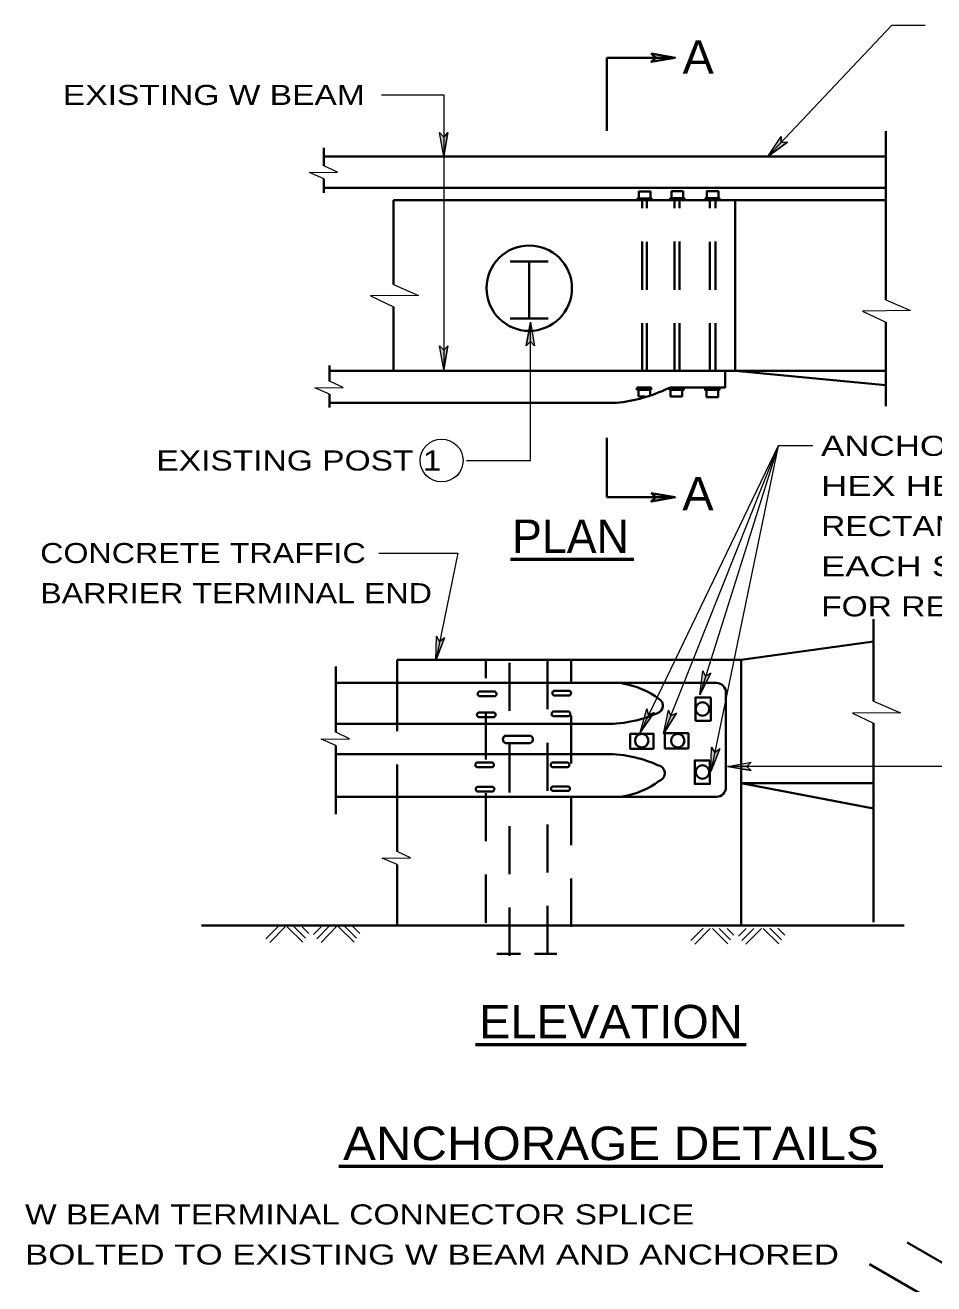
# Model space of a CAD drawing. Extents: x 12.4 to 19.52, y 6.05 to 15.92.
# Drawn here: x 12.402 to 15.119, y 12.12 to 15.885 of the extents above; entities that cross this region are included whole.
import ezdxf
from ezdxf.enums import TextEntityAlignment as Align

# ---------------------------------------------------------------- set-up
doc = ezdxf.new("R2010")
doc.units = 0
doc.header["$LTSCALE"] = 0.024
doc.linetypes.add('LONG_DASHED', pattern=[7.5, 6, -1.5])
for name, color, linetype, lineweight in [('1', 7, 'Continuous', 35), ('10', 7, 'Continuous', 13), ('12', 7, 'Continuous', 53), ('6', 7, 'Continuous', 13)]:
    doc.layers.add(name, color=color, linetype=linetype, lineweight=lineweight)

msp = doc.modelspace()

# ---------------------------------------------------------------- hatches: boundary and pattern name
at = {"layer": '10'}
for points in [[(14.274, 15.7998), (14.3455, 15.7872), (14.274, 15.7746), (14.2875, 15.7872)], [(13.6661, 15.5633), (13.6535, 15.4918), (13.6409, 15.5633), (13.6535, 15.5498)], [(14.6812, 15.5348), (14.623, 15.4914), (14.6629, 15.5521), (14.6628, 15.5336)], [(13.9001, 14.9254), (13.9127, 14.9969), (13.9253, 14.9254), (13.9127, 14.9389)], [(13.6661, 14.9258), (13.6535, 14.8543), (13.6409, 14.9258), (13.6535, 14.9123)], [(14.274, 14.4853), (14.3455, 14.4727), (14.274, 14.4601), (14.2875, 14.4727)], [(13.6562, 14.0519), (13.6294, 13.9844), (13.6316, 14.057), (13.6412, 14.0412)], [(14.4526, 13.9464), (14.4191, 13.882), (14.4286, 13.954), (14.4365, 13.9373)], [(14.2832, 13.8286), (14.2408, 13.7697), (14.2605, 13.8396), (14.266, 13.8219)], [(14.3493, 13.8269), (14.3112, 13.7651), (14.3259, 13.8362), (14.3326, 13.819)], [(14.4788, 13.7203), (14.452, 13.6528), (14.4542, 13.7254), (14.4638, 13.7096)], [(14.5733, 13.6555), (14.5018, 13.6681), (14.5733, 13.6807), (14.5598, 13.6681)]]:
    msp.add_hatch(color=256, dxfattribs=at).paths.add_polyline_path(points)

# ---------------------------------------------------------------- linework, layer by layer
at = {"layer": '1'}
for p, q in [((14.9755, 15.5677), (14.9755, 15.0633)), ((13.2949, 15.4643), (13.2949, 15.5174)), ((14.9775, 15.4918), (13.2949, 15.4918)), ((13.2949, 15.3833), (13.2949, 15.4253)), ((14.9775, 15.3981), (13.2949, 15.3981)), ((14.5254, 15.3617), (13.5037, 15.3617)), ((13.5037, 15.3617), (13.5037, 15.1093)), ((14.5254, 14.8508), (14.5254, 15.3617)), ((14.5254, 15.3617), (14.8546, 15.3617)), ((14.9755, 15.3617), (14.8546, 15.3617)), ((13.9658, 15.178), (13.909, 15.178)), ((13.5037, 14.8536), (13.5037, 15.0427)), ((13.9658, 15.0077), (13.8522, 15.0077)), ((14.9755, 14.7454), (14.9755, 14.9966)), ((13.3116, 14.8203), (13.3116, 14.8664)), ((14.5254, 14.8508), (13.3129, 14.8508)), ((14.5254, 14.8508), (14.9755, 14.8508)), ((14.5254, 14.8508), (14.9755, 14.8084)), ((13.3116, 14.7814), (13.3116, 14.741)), ((13.3129, 14.755), (14.1694, 14.755)), ((14.9386, 14.1082), (14.9386, 13.8634)), ((13.3305, 13.9671), (13.3305, 13.77)), ((14.5425, 13.9869), (13.5142, 13.9869)), ((14.469, 13.9175), (13.3305, 13.9175)), ((13.8059, 13.8916), (13.7607, 13.8916)), ((14.029, 13.8941), (13.9838, 13.8941)), ((13.7607, 13.8778), (13.8059, 13.8778)), ((13.9838, 13.8804), (14.029, 13.8804)), ((14.4974, 13.6052), (14.4974, 13.889)), ((13.8034, 13.8291), (13.7582, 13.8291)), ((13.7582, 13.8154), (13.8034, 13.8154)), ((14.0266, 13.8317), (13.9813, 13.8317)), ((13.9813, 13.818), (14.0266, 13.818)), ((14.1285, 13.7951), (13.3305, 13.7951)), ((14.9386, 13.2019), (14.9386, 13.797)), ((13.9115, 13.7597), (13.8388, 13.7597)), ((13.3305, 13.5248), (13.3305, 13.7307)), ((14.1285, 13.7043), (13.3305, 13.7043)), ((13.8388, 13.7377), (13.9115, 13.7377)), ((13.7984, 13.6793), (13.7532, 13.6793)), ((13.7532, 13.6655), (13.7984, 13.6655)), ((14.0241, 13.6793), (13.9789, 13.6793)), ((13.9789, 13.6655), (14.0241, 13.6655)), ((13.7996, 13.6068), (13.7545, 13.6068)), ((13.7545, 13.5932), (13.7996, 13.5932)), ((14.0253, 13.6082), (13.9801, 13.6082)), ((13.9801, 13.5944), (14.0253, 13.5944)), ((14.5425, 13.6179), (14.9386, 13.6179)), ((14.5425, 13.6179), (14.9386, 13.5418)), ((14.469, 13.5769), (13.3305, 13.5769)), ((13.5142, 13.5769), (13.5142, 13.4134)), ((15.0302, 13.1922), (12.9294, 13.1922)), ((13.8124, 13.1075), (13.8833, 13.1075)), ((13.9918, 13.1075), (13.9251, 13.1075)), ((15.2677, 12.1125), (15.0393, 12.2444)), ((14.9268, 12.1793), (15.1538, 12.0482))]:
    msp.add_line(p, q, dxfattribs=at)
at = {"layer": '1', "linetype": 'LONG_DASHED'}
for p, q in [((14.2466, 14.8495), (14.2466, 15.3604)), ((14.2605, 14.849), (14.2605, 15.3604)), ((14.4497, 14.849), (14.4497, 15.3604)), ((14.2737, 14.8009), (14.2306, 14.8009)), ((14.236, 14.7738), (14.236, 14.794)), ((14.2705, 14.794), (14.2705, 14.7796)), ((14.236, 14.7738), (14.2561, 14.7738)), ((13.7795, 13.2002), (13.7795, 13.9869)), ((13.8502, 13.1016), (13.8502, 13.9869)), ((13.9638, 13.1066), (13.9638, 13.9869)), ((14.035, 13.1886), (14.035, 13.9869)), ((13.5142, 13.9175), (13.5142, 13.5769))]:
    msp.add_line(p, q, dxfattribs=at)
at = {"layer": '1', "linetype": 'LONG_DASHED', "lineweight": 40}
for p, q in [((14.3438, 14.8495), (14.3438, 15.3604)), ((14.3582, 14.8495), (14.3582, 15.3604)), ((14.4667, 14.8495), (14.4667, 15.3604))]:
    msp.add_line(p, q, dxfattribs=at)
at = {"layer": '1', "lineweight": 40}
for p, q in [((13.5142, 13.9869), (13.5142, 13.9175)), ((13.5142, 13.1922), (13.5142, 13.3741))]:
    msp.add_line(p, q, dxfattribs=at)
at = {"layer": '1'}
for points in [[(14.2756, 15.3598), (14.2756, 15.3662), (14.2329, 15.3662), (14.2329, 15.3604)], [(14.2717, 15.3673), (14.2717, 15.3875), (14.2372, 15.3875), (14.2372, 15.3673)], [(14.3733, 15.3605), (14.3733, 15.3668), (14.3307, 15.3668), (14.3307, 15.3609)], [(14.3695, 15.368), (14.3695, 15.3881), (14.335, 15.3881), (14.335, 15.368)], [(14.4748, 15.368), (14.4748, 15.3881), (14.4403, 15.3881), (14.4403, 15.368)], [(13.909, 15.0077), (13.909, 15.178), (13.8522, 15.178)], [(14.4953, 14.8508), (14.4953, 14.8013), (14.3374, 14.8013)], [(14.3715, 14.8009), (14.3715, 14.7944), (14.3288, 14.7944), (14.3288, 14.8003)], [(14.3665, 14.7945), (14.3665, 14.7745), (14.332, 14.7745), (14.332, 14.7945)], [(14.4781, 14.8002), (14.4781, 14.7938), (14.4352, 14.7938), (14.4352, 14.7998)], [(14.4742, 14.7927), (14.4742, 14.7725), (14.4397, 14.7725), (14.4397, 14.7927)], [(14.5425, 13.1922), (14.5425, 13.9869), (14.9386, 14.0415)]]:
    msp.add_lwpolyline(points, dxfattribs=at)
at = {"layer": '1', "lineweight": 40}
msp.add_lwpolyline([(14.4786, 15.3605), (14.4786, 15.3668), (14.4359, 15.3668), (14.4359, 15.3609)], dxfattribs=at)
at = {"layer": '1', "linetype": 'LONG_DASHED'}
msp.add_lwpolyline([(14.2737, 14.8009), (14.2737, 14.7944), (14.231, 14.7944), (14.231, 14.8003)], dxfattribs=at)
at = {"layer": '1'}
for points in [[(14.4518, 13.8742), (14.4066, 13.8742), (14.4066, 13.8043), (14.4518, 13.8043)], [(14.2811, 13.7204), (14.2811, 13.7656), (14.2112, 13.7656), (14.2112, 13.7204)], [(14.3851, 13.7216), (14.3851, 13.7668), (14.3152, 13.7668), (14.3152, 13.7216)], [(14.4493, 13.6856), (14.4041, 13.6856), (14.4041, 13.6157), (14.4493, 13.6157)]]:
    msp.add_lwpolyline(points, close=True, dxfattribs=at)
for centre, radius in [((13.90922, 15.09802), 0.12771), ((14.42736, 13.83965), 0.02006), ((14.2456, 13.74474), 0.02006), ((14.3534, 13.74474), 0.02006), ((14.42736, 13.65107), 0.02006)]:
    msp.add_circle(centre, radius, dxfattribs=at)
for centre, radius, start, end in [((14.12122, 15.22507), 0.47253, 275.86093, 295.61269), ((14.33662, 14.77306), 0.02819, 88.40312, 113.24387), ((13.76247, 13.88474), 0.00709, 104.26276, 255.73723), ((13.80416, 13.88474), 0.00709, 284.26277, 75.73723), ((13.9856, 13.88724), 0.00709, 104.26276, 255.73723), ((14.02729, 13.88724), 0.00709, 284.26277, 75.73723), ((14.15096, 13.67485), 0.24349, 52.96175, 81.11338), ((13.75996, 13.82229), 0.00709, 104.26276, 255.73723), ((13.80166, 13.82229), 0.00709, 284.26277, 75.73723), ((13.98309, 13.82479), 0.00709, 104.26276, 255.73723), ((14.02479, 13.82479), 0.00709, 284.26277, 75.73723), ((14.14186, 14.15937), 0.36457, 267.88419, 294.42415), ((13.84154, 13.74878), 0.01141, 104.26276, 255.73723), ((13.90869, 13.74878), 0.01141, 284.26277, 75.73723), ((14.14186, 13.33995), 0.36457, 65.57585, 92.11581), ((13.75495, 13.67242), 0.00709, 104.26276, 255.73723), ((13.79665, 13.67242), 0.00709, 284.26277, 75.73723), ((13.98058, 13.67242), 0.00709, 104.26276, 255.73723), ((14.02228, 13.67242), 0.00709, 284.26277, 75.73723), ((14.29018, 13.64764), 0.02437, 287.78002, 84.27857), ((13.7562, 13.59998), 0.00709, 104.26276, 255.73723), ((13.7979, 13.59998), 0.00709, 284.26277, 75.73723), ((13.98184, 13.60123), 0.00709, 104.26276, 255.73723), ((14.02353, 13.60123), 0.00709, 284.26277, 75.73723), ((14.15096, 13.81879), 0.24349, 278.88662, 307.03825), ((14.469, 13.60527), 0.02838, 270, 0)]:
    msp.add_arc(centre, radius, start, end, dxfattribs=at)
at = {"layer": '1', "lineweight": 40}
for centre, radius, start, end in [((14.469, 13.88906), 0.02838, 0.00001, 90), ((14.28617, 13.84939), 0.02289, 286.33968, 59.98052)]:
    msp.add_arc(centre, radius, start, end, dxfattribs=at)
at = {"layer": '10'}
for p, q in [((14.9936, 15.8846), (14.623, 15.4914)), ((14.9936, 15.8846), (15.0937, 15.8846)), ((13.4673, 15.676), (13.6535, 15.676)), ((13.6535, 15.676), (13.6535, 15.4918)), ((13.6535, 15.4918), (13.6409, 15.5633)), ((13.6535, 15.4918), (13.6661, 15.5633)), ((14.623, 15.4914), (14.6629, 15.5521)), ((14.623, 15.4914), (14.6812, 15.5348)), ((13.6535, 15.4904), (13.6535, 14.8543)), ((13.9127, 14.9969), (13.9001, 14.9254)), ((13.9127, 14.9969), (13.9253, 14.9254)), ((13.6535, 14.8543), (13.6409, 14.9258)), ((13.6535, 14.8543), (13.6661, 14.9258)), ((14.6538, 14.6266), (14.2408, 13.7697)), ((14.6538, 14.6266), (14.3112, 13.7651)), ((14.6538, 14.6266), (14.4191, 13.882)), ((14.6538, 14.6266), (14.452, 13.6528)), ((14.7571, 14.6266), (14.6538, 14.6266)), ((13.4598, 14.3059), (13.696, 14.3059)), ((13.696, 14.3059), (13.6294, 13.9844)), ((13.6294, 13.9844), (13.6316, 14.057)), ((13.6294, 13.9844), (13.6562, 14.0519)), ((14.4191, 13.882), (14.4286, 13.954)), ((14.4191, 13.882), (14.4526, 13.9464)), ((14.2408, 13.7697), (14.2605, 13.8396)), ((14.2408, 13.7697), (14.2832, 13.8286)), ((14.3112, 13.7651), (14.3259, 13.8362)), ((14.3112, 13.7651), (14.3493, 13.8269)), ((14.452, 13.6528), (14.4542, 13.7254)), ((14.452, 13.6528), (14.4788, 13.7203)), ((14.5018, 13.6681), (14.5733, 13.6807)), ((15.1938, 13.6681), (14.5018, 13.6681)), ((14.5018, 13.6681), (14.5733, 13.6555)), ((13.5544, 13.3943), (13.5142, 13.4134)), ((13.4695, 13.3936), (13.5544, 13.3943)), ((13.5142, 13.3741), (13.4695, 13.3936))]:
    msp.add_line(p, q, dxfattribs=at)
at = {"layer": '10', "lineweight": 35}
for p, q in [((14.1415, 15.7872), (14.3455, 15.7872)), ((14.1415, 15.7872), (14.1415, 15.5684)), ((14.3455, 15.7872), (14.274, 15.7998)), ((14.3455, 15.7872), (14.274, 15.7746)), ((14.1415, 14.4727), (14.1415, 14.6504)), ((14.1415, 14.4727), (14.3455, 14.4727)), ((14.3455, 14.4727), (14.274, 14.4853)), ((14.3455, 14.4727), (14.274, 14.4601))]:
    msp.add_line(p, q, dxfattribs=at)
for points in [[(14.274, 15.7998), (14.2875, 15.7872), (14.274, 15.7746)], [(14.274, 14.4853), (14.2875, 14.4727), (14.274, 14.4601)]]:
    msp.add_lwpolyline(points, dxfattribs=at)
for points in [[(14.274, 15.7998), (14.3455, 15.7872), (14.274, 15.7746), (14.2875, 15.7872)], [(14.274, 14.4853), (14.3455, 14.4727), (14.274, 14.4601), (14.2875, 14.4727)]]:
    msp.add_lwpolyline(points, close=True, dxfattribs=at)
at = {"layer": '10'}
for points in [[(13.6661, 15.5633), (13.6535, 15.5498), (13.6409, 15.5633)], [(14.6812, 15.5348), (14.6628, 15.5336), (14.6629, 15.5521)], [(13.2949, 15.4253), (13.2518, 15.4441), (13.3359, 15.4448), (13.2949, 15.4643)], [(13.5037, 15.1093), (13.5784, 15.0766), (13.4347, 15.0755), (13.5037, 15.0427)], [(14.9755, 15.0633), (15.0496, 15.0309), (14.9059, 15.0298), (14.9755, 14.9966)], [(13.7217, 14.5827), (13.9127, 14.5827), (13.9127, 14.9969)], [(13.6661, 14.9258), (13.6535, 14.9123), (13.6409, 14.9258)], [(13.9001, 14.9254), (13.9127, 14.9389), (13.9253, 14.9254)], [(13.3116, 14.7814), (13.2685, 14.8002), (13.3526, 14.8009), (13.3116, 14.8203)], [(13.6562, 14.0519), (13.6412, 14.0412), (13.6316, 14.057)], [(14.4526, 13.9464), (14.4365, 13.9373), (14.4286, 13.954)], [(14.9386, 13.8634), (15.0197, 13.8279), (14.876, 13.8268), (14.9386, 13.797)], [(14.2832, 13.8286), (14.266, 13.8219), (14.2605, 13.8396)], [(14.3493, 13.8269), (14.3326, 13.819), (14.3259, 13.8362)], [(13.3305, 13.7307), (13.287, 13.7497), (13.3719, 13.7504), (13.3305, 13.77)], [(14.4788, 13.7203), (14.4638, 13.7096), (14.4542, 13.7254)], [(14.5733, 13.6555), (14.5598, 13.6681), (14.5733, 13.6807)]]:
    msp.add_lwpolyline(points, dxfattribs=at)
for points in [[(13.6661, 15.5633), (13.6535, 15.4918), (13.6409, 15.5633), (13.6535, 15.5498)], [(14.6812, 15.5348), (14.623, 15.4914), (14.6629, 15.5521), (14.6628, 15.5336)], [(13.9001, 14.9254), (13.9127, 14.9969), (13.9253, 14.9254), (13.9127, 14.9389)], [(13.6661, 14.9258), (13.6535, 14.8543), (13.6409, 14.9258), (13.6535, 14.9123)], [(13.6562, 14.0519), (13.6294, 13.9844), (13.6316, 14.057), (13.6412, 14.0412)], [(14.4526, 13.9464), (14.4191, 13.882), (14.4286, 13.954), (14.4365, 13.9373)], [(14.2832, 13.8286), (14.2408, 13.7697), (14.2605, 13.8396), (14.266, 13.8219)], [(14.3493, 13.8269), (14.3112, 13.7651), (14.3259, 13.8362), (14.3326, 13.819)], [(14.4788, 13.7203), (14.452, 13.6528), (14.4542, 13.7254), (14.4638, 13.7096)], [(14.5733, 13.6555), (14.5018, 13.6681), (14.5733, 13.6807), (14.5598, 13.6681)]]:
    msp.add_lwpolyline(points, close=True, dxfattribs=at)
msp.add_circle((13.6472, 14.5827), 0.06414, dxfattribs=at)
at = {"layer": '12'}
for p, q in [((13.8533, 14.2876), (14.222, 14.2876)), ((13.7486, 12.836), (14.5584, 12.836)), ((13.3401, 12.472), (14.9669, 12.472))]:
    msp.add_line(p, q, dxfattribs=at)
at = {"layer": '6'}
for p, q in [((13.1581, 13.1891), (13.1217, 13.1521)), ((13.1339, 13.1413), (13.1797, 13.1879)), ((13.1857, 13.188), (13.2326, 13.142)), ((13.2403, 13.1546), (13.2062, 13.1882)), ((13.2298, 13.1883), (13.2503, 13.1681)), ((13.2638, 13.1652), (13.2868, 13.1885)), ((13.3103, 13.1887), (13.2743, 13.1522)), ((13.2865, 13.1413), (13.3331, 13.1888)), ((13.3375, 13.1889), (13.3852, 13.1421)), ((13.393, 13.1547), (13.3579, 13.189)), ((13.3814, 13.1891), (13.4029, 13.1681)), ((14.4292, 13.1839), (14.3927, 13.1468)), ((14.4049, 13.136), (14.4507, 13.1827)), ((14.4568, 13.1827), (14.5036, 13.1368)), ((14.5114, 13.1494), (14.4772, 13.1828)), ((14.5007, 13.183), (14.5213, 13.1628)), ((14.5348, 13.1599), (14.5578, 13.1833)), ((14.5813, 13.1834), (14.5453, 13.1468)), ((14.5574, 13.136), (14.6041, 13.1836)), ((14.6085, 13.1836), (14.6561, 13.1368)), ((14.6639, 13.1494), (14.6289, 13.1837)), ((14.6524, 13.1839), (14.6739, 13.1628))]:
    msp.add_line(p, q, dxfattribs=at)

# ---------------------------------------------------------------- texts
at = {"layer": '12'}
for s, height, width, p in [('A', 0.1, 1.05, (14.3676, 15.7391)), ('ANCHOR BOLTS 4-7/8" O GALV.', 0.06, 1.3, (14.7821, 14.5966)), ('A', 0.1, 1.05, (14.367, 14.4336)), ('HEX HEAD BOLTS, NUTS AND 8', 0.06, 1.35, (14.7821, 14.4766)), ('RECTANGULAR WASHERS 4 ON', 0.06, 1.25, (14.7821, 14.3566)), ('CONCRETE TRAFFIC', 0.06, 1.2, (12.4467, 14.2759)), ('EACH SIDE SEE STD. MD 605.41-02', 0.06, 1.35, (14.7821, 14.2366)), ('BARRIER TERMINAL END', 0.06, 1.2, (12.4467, 14.1559)), ('FOR RECTANGULAR WASHER DETAIL', 0.06, 1.25, (14.7821, 14.1166)), ('W BEAM TERMINAL CONNECTOR SPLICE', 0.06, 1.25, (12.4013, 12.2981)), ('BOLTED TO EXISTING W BEAM AND ANCHORED', 0.06, 1.3, (12.4013, 12.1781))]:
    msp.add_text(s, height=height, dxfattribs=dict(at, width=width)).set_placement(p)
at = {"layer": '12', "width": 1.25}
for s, p in [('EXISTING W BEAM', (13.4173, 15.646)), ('EXISTING POST 1', (13.6467, 14.5527))]:
    msp.add_text(s, height=0.06, dxfattribs=at).set_placement(p, align=Align.RIGHT)
at = {"layer": '12'}
msp.add_text('PLAN', height=0.1, dxfattribs=at).set_placement((14.03245, 14.3062), align=Align.CENTER)
for s, width, p in [('ELEVATION', 1.05, (14.1535, 12.8546)), ('ANCHORAGE DETAILS', 1.1, (14.15355, 12.4906))]:
    msp.add_text(s, height=0.1, dxfattribs=dict(at, width=width)).set_placement(p, align=Align.CENTER)

doc.saveas('drawing.dxf')
